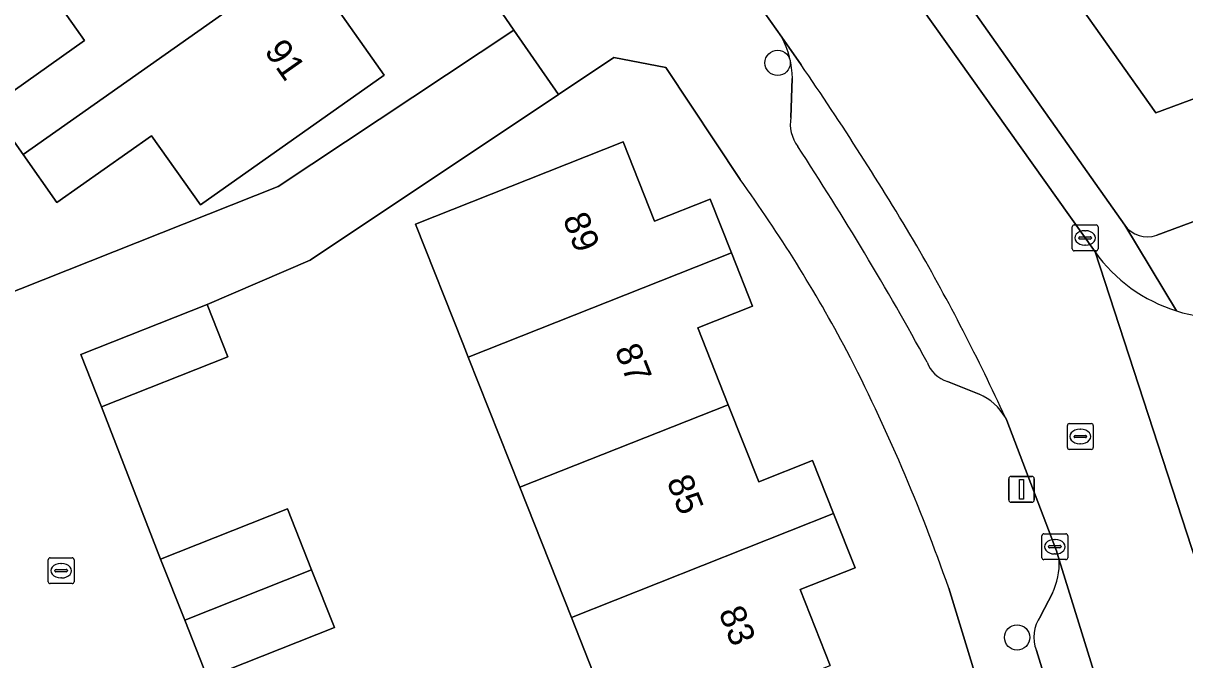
# Model space of a CAD drawing. Extents: x 158472 to 159562, y 388525 to 389606.
# Drawn here: x 159046.82 to 159091.78, y 388682.37 to 388706.99 of the extents above; entities that cross this region are included whole.
import ezdxf

# ---------------------------------------------------------------- set-up
doc = ezdxf.new("R2010")
doc.units = 0
for name, color, linetype in [('IMGEO_Boom', 7, 'Continuous'), ('IMGEO_Erf', 7, 'Continuous'), ('IMGEO_Kolk', 7, 'Continuous'), ('IMGEO_Lichtmast', 7, 'Continuous'), ('IMGEO_Pand', 7, 'Continuous'), ('IMGEO_Pand_nummerreeks', 7, 'Continuous'), ('IMGEO_Parkeervlak_open', 7, 'Continuous'), ('IMGEO_Rijbaan_lokaal_open', 7, 'Continuous'), ('IMGEO_Rioolput', 7, 'Continuous'), ('IMGEO_Voetpad_open', 7, 'Continuous')]:
    doc.layers.add(name, color=color, linetype=linetype)

msp = doc.modelspace()

# ---------------------------------------------------------------- linework, layer by layer
at = {"layer": 'IMGEO_Boom'}
for centre in [(159076.018, 388705.459), (159085.286, 388683.231)]:
    msp.add_circle(centre, 0.489, dxfattribs=at)
at = {"layer": 'IMGEO_Erf'}
for points in [[(159129.382, 388731.188), (159127.977, 388734.928), (159098.633, 388724.549), (159096.76, 388723.842), (159095.375, 388727.512), (159093.991, 388731.181), (159095.864, 388731.888), (159095.158, 388733.757), (159091.108, 388732.349), (159089.726, 388736.325), (159093.776, 388737.732), (159093.126, 388739.578), (159089.184, 388738.159), (159087.73, 388742.198), (159086.276, 388746.237), (159090.218, 388747.656), (159089.723, 388749.076), (159081.076, 388745.993), (159079.648, 388750), (159079.563, 388750.238), (159071.813, 388746.344), (159061.361, 388738.963), (159069.922, 388726.839), (159089.451, 388699.181)], [(159090.691, 388698.796), (159138.036, 388716.321), (159133.328, 388729.371), (159130.469, 388728.297), (159129.382, 388731.188)], [(159041.242, 388694.55), (159056.691, 388700.672), (159065.814, 388706.73), (159063.092, 388710.684), (159058.87, 388707.705), (159060.79, 388704.984), (159053.674, 388699.965), (159051.785, 388702.643), (159048.124, 388700.06), (159046.82, 388701.91), (159045.531, 388703.737), (159049.194, 388706.32), (159047.356, 388708.925), (159045.58, 388711.443)], [(159104.395, 388708.619), (159090.652, 388703.523), (159085.668, 388710.582)], [(159074.566, 388700.949), (159071.685, 388705.286), (159069.675, 388705.667), (159067.53, 388704.236), (159057.922, 388697.827), (159053.938, 388696.117), (159054.741, 388694.092), (159049.847, 388692.152), (159052.136, 388686.253), (159057.049, 388688.2), (159057.981, 388685.85), (159058.867, 388683.613), (159053.954, 388681.666)], [(159070.03, 388678.962), (159068.034, 388684), (159066.036, 388689.039), (159064.039, 388694.078), (159063.841, 388694.577), (159061.998, 388699.225), (159070.036, 388702.411), (159071.257, 388699.33), (159073.41, 388700.183), (159074.231, 388698.113), (159075.051, 388696.044), (159072.931, 388695.204), (159074.108, 388692.235), (159075.292, 388689.246), (159077.373, 388690.071), (159078.186, 388688.02), (159079.017, 388685.923), (159076.888, 388685.079), (159078.054, 388682.139)], [(159086.464, 388672.641), (159082.641, 388685.14)]]:
    msp.add_lwpolyline(points, dxfattribs=at)
for centre, radius, start, end in [((159028.091, 388667.378), 57.332, 28.02997, 35.8424), ((159090.32, 388699.791), 1.062, 215.0637, 290.4389), ((159014.276, 388661.213), 72.431, 19.28978, 27.19927)]:
    msp.add_arc(centre, radius, start, end, dxfattribs=at)
at = {"layer": 'IMGEO_Kolk'}
for p, q in [((159087.419, 388698.262), (159087.419, 388699.114)), ((159087.494, 388699.188), (159088.346, 388699.188)), ((159087.907, 388698.968), (159087.932, 388698.968)), ((159088.42, 388699.114), (159088.42, 388698.262)), ((159087.678, 388698.682), (159087.678, 388698.694)), ((159088.116, 388698.645), (159087.718, 388698.645)), ((159087.721, 388698.731), (159088.119, 388698.731)), ((159088.162, 388698.694), (159088.162, 388698.682)), ((159088.346, 388698.188), (159087.494, 388698.188)), ((159087.93, 388698.408), (159087.905, 388698.408)), ((159086.246, 388686.313), (159086.246, 388687.165)), ((159086.321, 388687.239), (159087.173, 388687.239)), ((159086.734, 388687.019), (159086.759, 388687.019)), ((159087.247, 388687.165), (159087.247, 388686.313)), ((159086.505, 388686.733), (159086.505, 388686.745)), ((159086.943, 388686.696), (159086.545, 388686.696)), ((159086.548, 388686.782), (159086.946, 388686.782)), ((159086.757, 388686.459), (159086.732, 388686.459)), ((159086.989, 388686.745), (159086.989, 388686.733)), ((159047.785, 388685.386), (159047.785, 388686.238)), ((159047.86, 388686.312), (159048.712, 388686.312)), ((159048.273, 388686.092), (159048.298, 388686.092)), ((159048.786, 388686.238), (159048.786, 388685.386)), ((159087.173, 388686.239), (159086.321, 388686.239)), ((159048.044, 388685.806), (159048.044, 388685.818)), ((159048.482, 388685.769), (159048.084, 388685.769)), ((159048.087, 388685.855), (159048.485, 388685.855)), ((159048.296, 388685.532), (159048.271, 388685.532)), ((159048.528, 388685.818), (159048.528, 388685.806)), ((159048.712, 388685.312), (159047.86, 388685.312))]:
    msp.add_line(p, q, dxfattribs=at)
for points in [[(159087.419, 388698.262), (159087.419, 388699.114)], [(159087.494, 388699.188), (159088.346, 388699.188)], [(159088.42, 388699.114), (159088.42, 388698.262)], [(159088.346, 388698.188), (159087.494, 388698.188)], [(159086.246, 388686.313), (159086.246, 388687.165)], [(159086.321, 388687.239), (159087.173, 388687.239)], [(159087.247, 388687.165), (159087.247, 388686.313)], [(159047.785, 388685.386), (159047.785, 388686.238)], [(159047.86, 388686.312), (159048.712, 388686.312)], [(159048.786, 388686.238), (159048.786, 388685.386)], [(159087.173, 388686.239), (159086.321, 388686.239)], [(159048.712, 388685.312), (159047.86, 388685.312)]]:
    msp.add_lwpolyline(points, dxfattribs=at)
for centre, radius, start, end in [((159087.496, 388699.112), 0.0765, 91.552, 178.448), ((159087.496, 388699.112), 0.0765, 91.552, 178.448), ((159088.344, 388699.112), 0.0765, 1.552, 88.448), ((159088.344, 388699.112), 0.0765, 1.552, 88.448), ((159087.718, 388698.691), 0.0403, 85.8775, 175.7526), ((159087.715, 388698.681), 0.0366, 178.938, 274.7102), ((159088.119, 388698.688), 0.043, 264.8664, 352.4533), ((159088.123, 388698.693), 0.0386, 1.7309, 96.639), ((159087.496, 388698.264), 0.0765, 181.552, 268.448), ((159087.496, 388698.264), 0.0765, 181.552, 268.448), ((159088.344, 388698.264), 0.0765, 271.552, 358.448), ((159088.344, 388698.264), 0.0765, 271.552, 358.448), ((159086.323, 388687.163), 0.0765, 91.552, 178.448), ((159086.323, 388687.163), 0.0765, 91.552, 178.448), ((159087.171, 388687.163), 0.0765, 1.552, 88.448), ((159087.171, 388687.163), 0.0765, 1.552, 88.448), ((159086.545, 388686.742), 0.0403, 85.8775, 175.7526), ((159086.542, 388686.732), 0.0366, 178.938, 274.7102), ((159086.946, 388686.739), 0.043, 264.8664, 352.4533), ((159086.95, 388686.744), 0.0386, 1.7309, 96.639), ((159047.862, 388686.236), 0.0765, 91.552, 178.448), ((159047.862, 388686.236), 0.0765, 91.552, 178.448), ((159048.71, 388686.236), 0.0765, 1.552, 88.448), ((159048.71, 388686.236), 0.0765, 1.552, 88.448), ((159086.323, 388686.315), 0.0765, 181.552, 268.448), ((159086.323, 388686.315), 0.0765, 181.552, 268.448), ((159087.171, 388686.315), 0.0765, 271.552, 358.448), ((159087.171, 388686.315), 0.0765, 271.552, 358.448), ((159048.084, 388685.815), 0.0403, 85.8775, 175.7526), ((159048.081, 388685.805), 0.0366, 178.938, 274.7102), ((159048.485, 388685.812), 0.043, 264.8664, 352.4533), ((159048.489, 388685.817), 0.0386, 1.7309, 96.639), ((159047.862, 388685.388), 0.0765, 181.552, 268.448), ((159047.862, 388685.388), 0.0765, 181.552, 268.448), ((159048.71, 388685.388), 0.0765, 271.552, 358.448), ((159048.71, 388685.388), 0.0765, 271.552, 358.448)]:
    msp.add_arc(centre, radius, start, end, dxfattribs=at)
for centre, major_axis, ratio, start_param, end_param in [((159087.906, 388698.688), (-0.387, 0.002), 0.722429, 4.712389, 7.853982), ((159087.931, 388698.688), (-0.39, 0.002), 0.717154, 1.570796, 4.712389), ((159086.733, 388686.739), (-0.387, 0.002), 0.722429, 4.712389, 7.853982), ((159086.758, 388686.739), (-0.39, 0.002), 0.717154, 1.570796, 4.712389), ((159048.272, 388685.812), (-0.387, 0.002), 0.722429, 4.712389, 7.853982), ((159048.297, 388685.812), (-0.39, 0.002), 0.717154, 1.570796, 4.712389)]:
    msp.add_ellipse(centre, major_axis=major_axis, ratio=ratio, start_param=start_param, end_param=end_param, dxfattribs=at)
at = {"layer": 'IMGEO_Lichtmast'}
for p, q in [((159084.963, 388688.56), (159084.963, 388689.36)), ((159084.963, 388689.36), (159084.963, 388688.56)), ((159085.063, 388689.46), (159085.853, 388689.46)), ((159085.853, 388689.46), (159085.063, 388689.46)), ((159085.953, 388689.36), (159085.953, 388688.56)), ((159085.953, 388688.56), (159085.953, 388689.36)), ((159085.853, 388688.46), (159085.063, 388688.46)), ((159085.063, 388688.46), (159085.853, 388688.46))]:
    msp.add_line(p, q, dxfattribs=at)
msp.add_lwpolyline([(159085.383, 388689.335), (159085.533, 388689.335), (159085.533, 388688.585), (159085.383, 388688.585), (159085.383, 388689.335)], dxfattribs=at)
for centre, start, end in [((159085.063, 388689.36), 90, 180), ((159085.063, 388689.36), 90, 180), ((159085.853, 388689.36), 0, 90), ((159085.853, 388689.36), 360, 90), ((159085.063, 388688.56), 180, 270), ((159085.063, 388688.56), 180, 270), ((159085.853, 388688.56), 270, 0), ((159085.853, 388688.56), 270, 0)]:
    msp.add_arc(centre, 0.1, start, end, dxfattribs=at)
at = {"layer": 'IMGEO_Pand'}
for points in [[(159101.907, 388715.637), (159093.447, 388712.5), (159091.762, 388714.887), (159091.592, 388715.128), (159091.392, 388715.411), (159085.296, 388711.109), (159085.491, 388710.833), (159085.668, 388710.582), (159090.652, 388703.523), (159104.395, 388708.619)], [(159047.356, 388708.925), (159049.194, 388706.32), (159045.531, 388703.737), (159046.82, 388701.91), (159061.816, 388712.493), (159060.493, 388714.369), (159056.285, 388711.401), (159054.484, 388713.955)], [(159061.816, 388712.493), (159046.82, 388701.91), (159048.124, 388700.06), (159051.785, 388702.643), (159053.674, 388699.965), (159060.79, 388704.984), (159058.87, 388707.705), (159063.092, 388710.684)], [(159064.039, 388694.078), (159074.231, 388698.113), (159073.41, 388700.183), (159071.257, 388699.33), (159070.036, 388702.411), (159061.998, 388699.225), (159063.841, 388694.577)], [(159074.108, 388692.235), (159072.931, 388695.204), (159075.051, 388696.044), (159074.231, 388698.113), (159064.039, 388694.078), (159066.036, 388689.039)], [(159053.938, 388696.117), (159049.044, 388694.177), (159049.847, 388692.152), (159054.741, 388694.092)], [(159078.186, 388688.02), (159077.373, 388690.071), (159075.292, 388689.246), (159074.108, 388692.235), (159066.036, 388689.039), (159068.034, 388684)], [(159057.981, 388685.85), (159057.049, 388688.2), (159052.136, 388686.253), (159053.067, 388683.904)], [(159078.054, 388682.139), (159076.888, 388685.079), (159079.017, 388685.923), (159078.186, 388688.02), (159068.034, 388684), (159070.03, 388678.962)], [(159057.981, 388685.85), (159053.067, 388683.904), (159053.954, 388681.666), (159058.867, 388683.613)]]:
    msp.add_lwpolyline(points, close=True, dxfattribs=at)
at = {"layer": 'IMGEO_Parkeervlak_open'}
for points in [[(159076.93, 388705.384), (159076.181, 388706.456)], [(159076.587, 388704.854), (159076.532, 388703.348)], [(159082.588, 388693.135), (159083.819, 388692.643)], [(159090.978, 388673.275), (159090.622, 388674.39), (159090.538, 388674.651), (159089.719, 388677.213), (159086.912, 388686.226)], [(159086.652, 388684.945), (159086.193, 388684.051)], [(159086.035, 388682.725), (159087.906, 388676.644), (159088.177, 388675.794)]]:
    msp.add_lwpolyline(points, dxfattribs=at)
for centre, radius, start, end in [((159073.02, 388704.802), 3.568, 0.8288, 27.6137), ((158979.274, 388638.058), 118.614, 30.56753, 34.58317), ((159077.948, 388703.09), 1.44, 169.6728, 216.831), ((158978.128, 388637.375), 118.073, 28.59356, 33.31577), ((159010.471, 388657.575), 81.833, 24.67351, 29.90982), ((159082.957, 388694.312), 1.233, 200.3011, 252.6059), ((159082.963, 388690.665), 2.155, 29.7905, 66.5857), ((159084.321, 388686.085), 2.595, 333.9404, 3.113), ((159087.322, 388683.244), 1.388, 144.447, 201.9628)]:
    msp.add_arc(centre, radius, start, end, dxfattribs=at)
at = {"layer": 'IMGEO_Rijbaan_lokaal_open'}
for points in [[(159057, 388733.858), (159072.226, 388712.111), (159072.258, 388712.065), (159074.871, 388708.33), (159076.181, 388706.456), (159076.93, 388705.384)], [(159084.833, 388691.736), (159084.888, 388691.617), (159086.812, 388686.574), (159086.912, 388686.226), (159089.719, 388677.213), (159090.538, 388674.651), (159095.387, 388676.168), (159093.056, 388683.621), (159092.978, 388683.815), (159088.305, 388698.145), (159081.085, 388708.306), (159073.273, 388719.418)], [(159053.954, 388681.666), (159053.067, 388683.904), (159052.136, 388686.253), (159049.847, 388692.152), (159049.044, 388694.177), (159053.938, 388696.117), (159057.922, 388697.827), (159067.53, 388704.236), (159065.814, 388706.73), (159056.691, 388700.672), (159041.242, 388694.55), (159041.934, 388693.074), (159043.03, 388690.285), (159044.125, 388687.496), (159045.22, 388684.707), (159046.316, 388681.918)], [(159088.305, 388698.145), (159092.978, 388683.815), (159093.056, 388683.621)]]:
    msp.add_lwpolyline(points, dxfattribs=at)
for centre, radius, start, end in [((158979.274, 388638.058), 118.614, 30.56753, 34.58317), ((159010.471, 388657.575), 81.833, 24.67351, 29.90982), ((159093.247, 388701.654), 6.06, 215.3755, 252.8059), ((159093.252, 388701.668), 6.076, 252.7923, 290.1249)]:
    msp.add_arc(centre, radius, start, end, dxfattribs=at)
at = {"layer": 'IMGEO_Rioolput'}
for p, q in [((159087.233, 388690.576), (159087.233, 388691.428)), ((159087.308, 388691.502), (159088.16, 388691.502)), ((159088.234, 388691.428), (159088.234, 388690.576)), ((159087.492, 388690.996), (159087.492, 388691.008)), ((159087.93, 388690.959), (159087.532, 388690.959)), ((159087.535, 388691.045), (159087.933, 388691.045)), ((159087.721, 388691.282), (159087.746, 388691.282)), ((159087.976, 388691.008), (159087.976, 388690.996)), ((159088.16, 388690.502), (159087.308, 388690.502)), ((159087.744, 388690.722), (159087.719, 388690.722))]:
    msp.add_line(p, q, dxfattribs=at)
for points in [[(159087.233, 388690.576), (159087.233, 388691.428)], [(159087.308, 388691.502), (159088.16, 388691.502)], [(159088.234, 388691.428), (159088.234, 388690.576)], [(159088.16, 388690.502), (159087.308, 388690.502)]]:
    msp.add_lwpolyline(points, dxfattribs=at)
for centre, radius, start, end in [((159087.31, 388691.426), 0.0765, 91.552, 178.448), ((159087.31, 388691.426), 0.0765, 91.552, 178.448), ((159088.158, 388691.426), 0.0765, 1.552, 88.448), ((159088.158, 388691.426), 0.0765, 1.552, 88.448), ((159087.532, 388691.005), 0.0403, 85.8775, 175.7526), ((159087.529, 388690.995), 0.0366, 178.938, 274.7102), ((159087.933, 388691.002), 0.043, 264.8664, 352.4533), ((159087.937, 388691.007), 0.0386, 1.7309, 96.639), ((159087.31, 388690.578), 0.0765, 181.552, 268.448), ((159087.31, 388690.578), 0.0765, 181.552, 268.448), ((159088.158, 388690.578), 0.0765, 271.552, 358.448), ((159088.158, 388690.578), 0.0765, 271.552, 358.448)]:
    msp.add_arc(centre, radius, start, end, dxfattribs=at)
for centre, major_axis, ratio, start_param, end_param in [((159087.72, 388691.002), (-0.387, 0.002), 0.722429, 4.712389, 7.853982), ((159087.745, 388691.002), (-0.39, 0.002), 0.717154, 1.570796, 4.712389)]:
    msp.add_ellipse(centre, major_axis=major_axis, ratio=ratio, start_param=start_param, end_param=end_param, dxfattribs=at)
at = {"layer": 'IMGEO_Voetpad_open'}
for points in [[(159060.135, 388738.153), (159065.903, 388730.005), (159068.617, 388726.107), (159073.273, 388719.418), (159081.085, 388708.306), (159088.305, 388698.145)], [(159170.31, 388728.457), (159146.544, 388719.568), (159143.641, 388718.565), (159139.87, 388717.199), (159138.036, 388716.321), (159090.691, 388698.796)], [(159091.455, 388695.864), (159089.451, 388699.181), (159069.922, 388726.839)], [(159076.181, 388706.456), (159074.871, 388708.33), (159074.459, 388708.048), (159071.846, 388711.783), (159072.258, 388712.065), (159072.226, 388712.111)], [(159063.092, 388710.684), (159065.814, 388706.73), (159067.53, 388704.236), (159069.675, 388705.667), (159071.685, 388705.286), (159074.566, 388700.949)], [(159076.532, 388703.348), (159076.587, 388704.854)], [(159089.451, 388699.181), (159091.455, 388695.864)], [(159083.819, 388692.643), (159082.588, 388693.135)], [(159086.812, 388686.574), (159084.888, 388691.617), (159084.833, 388691.736)], [(159086.912, 388686.226), (159086.812, 388686.574)], [(159082.641, 388685.14), (159086.464, 388672.641), (159085.199, 388672.109), (159085.76, 388670.387), (159090.232, 388671.764)], [(159086.193, 388684.051), (159086.652, 388684.945)], [(159088.177, 388675.794), (159087.906, 388676.644), (159086.035, 388682.725)]]:
    msp.add_lwpolyline(points, dxfattribs=at)
for centre, radius, start, end in [((159073.02, 388704.802), 3.568, 0.8288, 27.6137), ((159077.948, 388703.09), 1.44, 169.6728, 216.831), ((158978.128, 388637.375), 118.073, 28.59356, 33.31577), ((159028.091, 388667.378), 57.332, 28.02997, 35.8424), ((159090.32, 388699.791), 1.062, 215.0637, 290.4389), ((159093.247, 388701.654), 6.06, 215.3755, 252.8059), ((159093.252, 388701.668), 6.076, 252.7923, 290.1249), ((159014.276, 388661.213), 72.431, 19.28978, 27.19927), ((159082.957, 388694.312), 1.233, 200.3011, 252.6059), ((159082.963, 388690.665), 2.155, 29.7905, 66.5857), ((159084.321, 388686.085), 2.595, 333.9404, 3.113), ((159087.322, 388683.244), 1.388, 144.447, 201.9628)]:
    msp.add_arc(centre, radius, start, end, dxfattribs=at)

# ---------------------------------------------------------------- texts
at = {"layer": 'IMGEO_Pand_nummerreeks'}
for s, rotation, p in [('91', 305.1432, (159056.125, 388705.913)), ('89', 291.6179, (159067.688, 388699.434)), ('87', 291.6179, (159069.699, 388694.358)), ('85', 291.6179, (159071.711, 388689.282)), ('83', 291.6179, (159073.722, 388684.206))]:
    msp.add_text(s, height=1, rotation=rotation, dxfattribs=at).set_placement(p)

doc.saveas('drawing.dxf')
